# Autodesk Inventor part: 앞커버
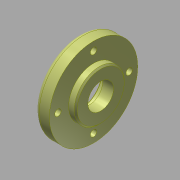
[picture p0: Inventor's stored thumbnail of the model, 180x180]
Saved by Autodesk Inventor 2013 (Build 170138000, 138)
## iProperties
Created: 2015-12
Part Number: 앞커버
Document SubType Name: Modeling
Designer: mdu
Density: 2.71 g/cm^3
Material: 알루미늄 6061
Mass: 70.9316 g
Surface Area: 93.9278 cm^2
Volume: 26.174 cm^3
Author: mdu
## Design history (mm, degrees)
sketch "스케치1"
  geometry: L1 (-7.5, 0)-(7.5, 0); L2 (-7.5, 0)-(-7.5, 31); L3 (-7.5, 31)-(2.5, 31); L4 (2.5, 31)-(2.5, 17.5); L5 (2.5, 17.5)-(7.5, 17.5); L6 (7.5, 17.5)-(7.5, 0); 2 further points
  constraints: 12 end point, 3 perpendicular, 1 coincident, 1 horizontal, 1 midpoint, 1 parallel
  dimensions: "d0" = 15 distance of L1.start L1.end; "d1" = 62 diameter of L3 L1; "d2" = 35 diameter of L5 L1; "d5" = 10 distance of L2.end L3.end
revolve "회전1" sketch "스케치1" stored, may be unused: angle "d6" = 90 deg
sketch "스케치2" dims "d42" = 50
  geometry: 3 further points
  constraints: 2 vertical alignment, 1 coincident, 2 other
hole "구멍1" sketch "스케치2" at (0, 25) diameter "d8" = 4.5; stored, may be unused: countersink angle "d12" = 90 deg, drill point angle "d14" = 118 deg; dims "d9" = 6, "d10" = 8, "d11" = 4.4, "d13" = 8
hole "구멍2" diameter "d20" = 18; stored, may be unused: countersink angle "d24" = 90 deg, drill point angle "d26" = 0 deg; dims "d18" = 10, "d19" = 10, "d21" = 6, "d22" = 8, "d23" = 4.4, "d25" = 8
hole "구멍3" diameter "d34" = 30; stored, may be unused: countersink angle "d38" = 90 deg, drill point angle "d40" = 0 deg; dims "d32" = 10, "d33" = 10, "d35" = 6, "d36" = 4, "d37" = 2, "d39" = 7.3
fillet "모깎기1" dims "d27" = 3, "d41" = 0.3
chamfer "모따기1" distance "d29" = 1; stored, may be unused: second distance "d30" = 2, angle "d31" = 45 deg
node "솔리드1"
pattern_circular "원형 패턴1" dims angle "d16" = 360 deg
